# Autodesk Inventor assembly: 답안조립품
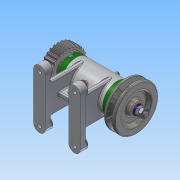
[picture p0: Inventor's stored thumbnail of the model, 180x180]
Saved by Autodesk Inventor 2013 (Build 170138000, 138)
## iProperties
Created: 2015-11
Part Number: 답안조립품
Document SubType Name: Assembly
Designer: Administrator
Author: Administrator
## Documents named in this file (16)
- C:\Users\Administrator\Desktop\451110V1047\답안조립품.iam
- C:\Users\Administrator\Desktop\451110V1047\본체.ipt
- C:\Users\Administrator\Desktop\451110V1047\V벨트풀리.ipt
- C:\Users\Administrator\Desktop\451110V1047\너트 M 8.ipt
- C:\Users\Administrator\Desktop\451110V1047\니플 M 6 x 0.75.ipt
- C:\Users\Administrator\Desktop\451110V1047\베어링 15 x 32 x 9.ipt
- C:\Users\Administrator\Desktop\451110V1047\볼트 M 6 x 8.ipt
- C:\Users\Administrator\Desktop\451110V1047\볼트 M4 x 12.ipt
- C:\Users\Administrator\Desktop\451110V1047\스퍼기어.ipt
- C:\Users\Administrator\Desktop\451110V1047\스프링와셔 8.ipt
- C:\Users\Administrator\Desktop\451110V1047\오일 실 15 25 7.ipt
- C:\Users\Administrator\Desktop\451110V1047\와셔 6x11.5.ipt
- C:\Users\Administrator\Desktop\451110V1047\와셔 8x17.ipt
- C:\Users\Administrator\Desktop\451110V1047\축.ipt
- C:\Users\Administrator\Desktop\451110V1047\커버.ipt
- C:\Users\Administrator\Desktop\451110V1047\키 3 x 3 x 12.ipt
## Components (11 placed, 3 different names)
1. V벨트풀리:1
2. KS B 2023 6002 - 15 x 32 x 9:1
3. KS B 2023 6002 - 15 x 32 x 9:2
4. ISO 4762 M4 x 12:2
5. ISO 4762 M4 x 12:1
6. ISO 4762 M4 x 12:3
7. ISO 4762 M4 x 12:4
8. ISO 4762 M4 x 12:5
9. ISO 4762 M4 x 12:6
10. ISO 4762 M4 x 12:7
11. ISO 4762 M4 x 12:8
